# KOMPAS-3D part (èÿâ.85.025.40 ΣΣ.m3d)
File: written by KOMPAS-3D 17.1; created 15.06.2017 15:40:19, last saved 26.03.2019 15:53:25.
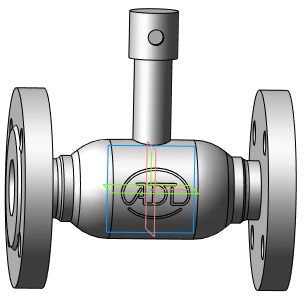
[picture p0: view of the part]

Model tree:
1. Операция без истории:2  (labels: Сталь 20  ГОСТ 1050-88)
